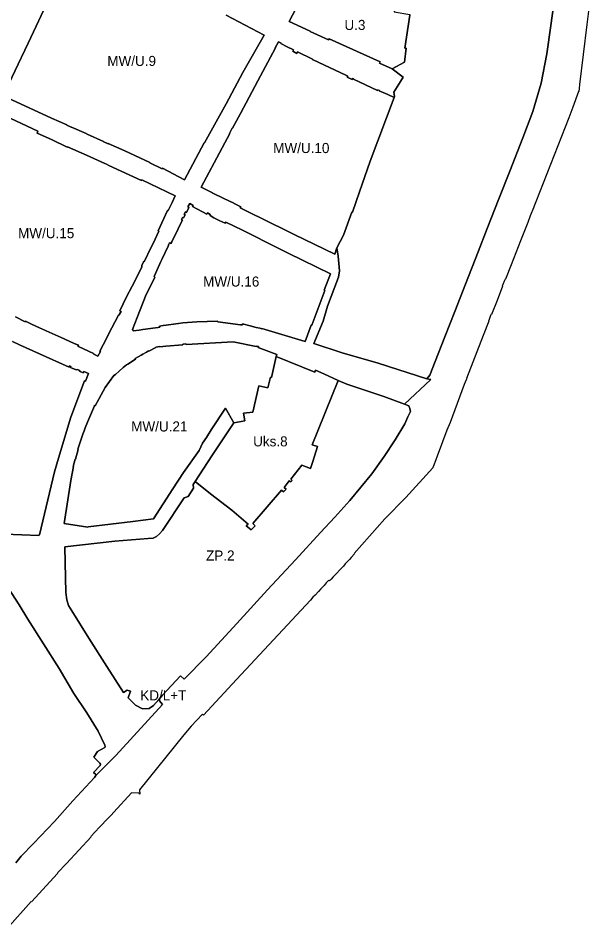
# Model space of a CAD drawing. Extents: x 7423367 to 7424726, y 5546744 to 5548391.
# Drawn here: x 7424194.2 to 7424477, y 5547495 to 5547946.7 of the extents above; entities that cross this region are included whole.
import ezdxf

# ---------------------------------------------------------------- set-up
doc = ezdxf.new("R2010")
doc.units = 0
doc.layers.add('linie_rozgraniczajace', color=7, linetype='Continuous')
doc.layers.add('oznaczenia_przeznaczen', color=7, linetype='Continuous')

msp = doc.modelspace()

# ---------------------------------------------------------------- linework, layer by layer
at = {"layer": 'linie_rozgraniczajace'}
for points in [[(7424328.44, 5547945.05), (7424336.81, 5547960.95), (7424338.1, 5547963.38), (7424338.61, 5547964.34), (7424348.19, 5547959.59), (7424348.95, 5547959.24), (7424350.58, 5547958.76), (7424363.05, 5547955.32), (7424375.68, 5547951.82), (7424380.63, 5547950.44), (7424380.54, 5547949.83), (7424388.26, 5547948.56), (7424388.22, 5547948.28), (7424385.9, 5547931.86), (7424386.56, 5547931.79), (7424385.59, 5547924.92), (7424379.57, 5547921.57), (7424373.24, 5547924.45), (7424373.56, 5547925.07), (7424348.32, 5547936.48), (7424348.05, 5547935.98), (7424338.85, 5547940.14), (7424338.9, 5547940.31)], [(7424284.85, 5547862.9), (7424295.29, 5547882.36), (7424299, 5547889.45), (7424298.86, 5547889.53), (7424300.27, 5547892.21), (7424300.41, 5547892.11), (7424304.33, 5547899.39), (7424312.89, 5547915.61), (7424321.74, 5547931.95), (7424321.57, 5547932.04), (7424323.14, 5547934.93), (7424324.51, 5547934.29), (7424324.4, 5547934.09), (7424327.56, 5547932.51), (7424330.67, 5547930.96), (7424330.33, 5547930.3), (7424332.21, 5547929.21), (7424332.66, 5547930), (7424340.05, 5547926.37), (7424340.26, 5547926.12), (7424340.42, 5547926.05), (7424356.49, 5547918.48), (7424357.58, 5547917.99), (7424357.31, 5547917.42), (7424359.66, 5547916.35), (7424359.91, 5547916.87), (7424360.4, 5547916.65), (7424360.35, 5547916.54), (7424372.26, 5547910.91), (7424372.41, 5547911.23), (7424373.24, 5547910.87), (7424373.16, 5547910.7), (7424377.39, 5547908.85), (7424380.46, 5547907.41), (7424368.61, 5547875.81), (7424363.27, 5547860.53), (7424359.94, 5547850.5), (7424359.58, 5547850.52), (7424355.45, 5547839.05), (7424352.18, 5547832.82), (7424351.08, 5547829.65), (7424330.92, 5547839.45), (7424313.97, 5547847.82), (7424310.72, 5547849.4), (7424304.18, 5547852.67), (7424304.44, 5547853.19), (7424301.24, 5547854.82), (7424301.02, 5547854.9), (7424296.04, 5547857.35), (7424296.01, 5547857.28), (7424290.36, 5547860.05), (7424290.4, 5547860.12)], [(7424250.75, 5547792.24), (7424253.18, 5547798.19), (7424257.58, 5547809.64), (7424258.88, 5547812.13), (7424261.88, 5547818.28), (7424261.51, 5547818.5), (7424264.91, 5547825.95), (7424265.37, 5547827.04), (7424268.63, 5547833.94), (7424268.55, 5547833.97), (7424269.17, 5547835.35), (7424269.88, 5547834.95), (7424270.34, 5547835.84), (7424273.5, 5547842.27), (7424273.42, 5547842.41), (7424275.53, 5547846.58), (7424275.06, 5547846.85), (7424275.62, 5547847.89), (7424276.17, 5547847.61), (7424276.96, 5547849.12), (7424276.4, 5547849.44), (7424277.01, 5547850.58), (7424277.56, 5547850.33), (7424278.81, 5547852.84), (7424278.28, 5547853.1), (7424279.2, 5547854.73), (7424280.92, 5547853.82), (7424280.63, 5547853.23), (7424287.63, 5547849.56), (7424287.93, 5547850.13), (7424289.39, 5547849.34), (7424289.28, 5547848.76), (7424291.05, 5547847.68), (7424293.75, 5547846.39), (7424296.72, 5547844.98), (7424297.03, 5547845.59), (7424305.29, 5547841.54), (7424309.98, 5547839.21), (7424318.74, 5547834.83), (7424328.06, 5547830.13), (7424348.93, 5547819.93), (7424345.89, 5547811.83), (7424346.19, 5547811.71), (7424339.76, 5547794.43), (7424339.45, 5547794.51), (7424336.47, 5547786.35), (7424314.94, 5547792.85), (7424314.89, 5547792.68), (7424313.96, 5547792.89), (7424312.18, 5547793.32), (7424309.21, 5547794.09), (7424305.37, 5547795.12), (7424305.32, 5547794.6), (7424304.43, 5547794.67), (7424293.04, 5547796.04), (7424292.94, 5547796.48), (7424282.68, 5547796.13), (7424275.75, 5547795.66), (7424275.71, 5547795.55), (7424273.67, 5547795.23), (7424272.26, 5547795.06), (7424267.58, 5547794.44), (7424265.99, 5547794.25), (7424264.27, 5547794), (7424264.31, 5547793.41), (7424263.6, 5547793.27), (7424262.17, 5547793.08), (7424255.89, 5547792.24), (7424254.12, 5547791.97), (7424251.26, 5547791.67)], [(7424250.75, 5547792.24), (7424251.26, 5547791.67), (7424254.12, 5547791.97), (7424255.89, 5547792.24), (7424262.17, 5547793.08), (7424263.6, 5547793.27), (7424264.31, 5547793.41), (7424264.27, 5547794), (7424265.99, 5547794.25), (7424267.58, 5547794.44), (7424272.26, 5547795.06), (7424273.67, 5547795.23), (7424275.71, 5547795.55), (7424275.75, 5547795.66), (7424282.68, 5547796.13), (7424292.94, 5547796.48), (7424293.04, 5547796.04), (7424304.43, 5547794.67), (7424305.32, 5547794.6), (7424305.37, 5547795.12), (7424309.21, 5547794.09), (7424312.18, 5547793.32), (7424313.96, 5547792.89), (7424314.89, 5547792.68), (7424314.94, 5547792.85), (7424336.47, 5547786.35), (7424339.45, 5547794.51), (7424339.76, 5547794.43), (7424346.19, 5547811.71), (7424345.89, 5547811.83), (7424348.93, 5547819.93), (7424328.06, 5547830.13), (7424318.74, 5547834.83), (7424309.98, 5547839.21), (7424305.29, 5547841.54), (7424297.03, 5547845.59), (7424296.72, 5547844.98), (7424293.75, 5547846.39), (7424291.05, 5547847.68), (7424289.28, 5547848.76), (7424289.39, 5547849.34), (7424287.93, 5547850.13), (7424287.63, 5547849.56), (7424280.63, 5547853.23), (7424280.92, 5547853.82), (7424279.2, 5547854.73), (7424278.28, 5547853.1), (7424278.81, 5547852.84), (7424277.56, 5547850.33), (7424277.01, 5547850.58), (7424276.4, 5547849.44), (7424276.96, 5547849.12), (7424276.17, 5547847.61), (7424275.62, 5547847.89), (7424275.06, 5547846.85), (7424275.53, 5547846.58), (7424273.42, 5547842.41), (7424273.5, 5547842.27), (7424270.34, 5547835.84), (7424269.88, 5547834.95), (7424269.17, 5547835.35), (7424268.55, 5547833.97), (7424268.63, 5547833.94), (7424265.37, 5547827.04), (7424264.91, 5547825.95), (7424261.51, 5547818.5), (7424261.88, 5547818.28), (7424258.88, 5547812.13), (7424257.58, 5547809.64), (7424253.18, 5547798.19)], [(7424216.89, 5547695.98), (7424220.27, 5547717.38), (7424221.53, 5547724.33), (7424221.34, 5547724.38), (7424222.43, 5547728), (7424222.59, 5547727.95), (7424223.94, 5547732.8), (7424223.68, 5547732.9), (7424226.2, 5547740.38), (7424226.82, 5547742.09), (7424227.37, 5547743.53), (7424228.52, 5547746.32), (7424231.89, 5547754.43), (7424231.99, 5547754.67), (7424232.38, 5547754.4), (7424237.23, 5547763.53), (7424241.59, 5547769.43), (7424242.36, 5547769.95), (7424244.21, 5547771.62), (7424246.26, 5547773.39), (7424247.86, 5547774.72), (7424248.43, 5547775.09), (7424252.35, 5547777.62), (7424252.21, 5547777.9), (7424255.05, 5547779.54), (7424255.98, 5547780.08), (7424257.8, 5547781.12), (7424258.82, 5547781.67), (7424258.87, 5547781.55), (7424262.38, 5547783.28), (7424262.3, 5547783.59), (7424264.28, 5547783.82), (7424264.3, 5547783.64), (7424267.32, 5547784), (7424275.74, 5547784.74), (7424275.73, 5547785.06), (7424277.32, 5547785.18), (7424277.34, 5547784.83), (7424300.65, 5547786.18), (7424312.19, 5547783.8), (7424312.29, 5547784.09), (7424313.22, 5547783.79), (7424313.12, 5547783.37), (7424322.35, 5547779.93), (7424322.03, 5547778.92), (7424319.65, 5547768.47), (7424319.2, 5547768.59), (7424317.95, 5547763.27), (7424313.42, 5547764.35), (7424310.44, 5547751.25), (7424305.79, 5547750.77), (7424306.43, 5547746.92), (7424301.08, 5547746.01), (7424296.95, 5547753.22), (7424289.84, 5547742.47), (7424287.5, 5547738.71), (7424285.48, 5547735.87), (7424283.9, 5547732.34), (7424276.07, 5547721.36), (7424270.83, 5547713.3), (7424261.22, 5547698.43), (7424251, 5547697.09), (7424228.77, 5547694.34), (7424228.74, 5547694.22)], [(7424281.91, 5547716.81), (7424290.17, 5547729.65), (7424301.08, 5547746.01), (7424306.43, 5547746.92), (7424305.79, 5547750.77), (7424310.44, 5547751.25), (7424313.42, 5547764.35), (7424317.95, 5547763.27), (7424319.2, 5547768.59), (7424319.65, 5547768.47), (7424322.03, 5547778.92), (7424341.12, 5547771.13), (7424341.5, 5547772.1), (7424345.6, 5547770.34), (7424352.75, 5547766.97), (7424339.96, 5547735.02), (7424342.57, 5547734.31), (7424340.16, 5547726.73), (7424338.99, 5547723.31), (7424334.71, 5547724.92), (7424329.32, 5547718.03), (7424329.99, 5547717.43), (7424329.3, 5547716.71), (7424328.56, 5547717.25), (7424325.99, 5547713.97), (7424326.96, 5547713.12), (7424325.73, 5547711.81), (7424324.73, 5547712.64), (7424310.42, 5547695.99), (7424311.63, 5547694.94), (7424309.63, 5547692.84), (7424307.17, 5547694.92), (7424308.12, 5547695.8), (7424300.12, 5547702.65), (7424289.49, 5547710.73)], [(7424217.84, 5547661.82), (7424217.47, 5547676.63), (7424217.33, 5547684.47), (7424242, 5547687.36), (7424258.62, 5547688.58), (7424261.1, 5547688.85), (7424262.66, 5547689.54), (7424264.25, 5547690.86), (7424265.65, 5547692.55), (7424276.37, 5547708.76), (7424278.42, 5547709.42), (7424281.08, 5547713.55), (7424280.94, 5547715.47), (7424281.91, 5547716.81), (7424289.49, 5547710.73), (7424300.12, 5547702.65), (7424308.12, 5547695.8), (7424307.17, 5547694.92), (7424309.63, 5547692.84), (7424311.63, 5547694.94), (7424310.42, 5547695.99), (7424324.73, 5547712.64), (7424325.73, 5547711.81), (7424326.96, 5547713.12), (7424325.99, 5547713.97), (7424328.56, 5547717.25), (7424329.3, 5547716.71), (7424329.99, 5547717.43), (7424329.32, 5547718.03), (7424334.71, 5547724.92), (7424338.99, 5547723.31), (7424340.16, 5547726.73), (7424342.57, 5547734.31), (7424339.96, 5547735.02), (7424352.75, 5547766.97), (7424357.12, 5547765.2), (7424369.44, 5547761.02), (7424375.45, 5547759), (7424385.71, 5547755.19), (7424387.84, 5547754.37), (7424388.35, 5547753.1), (7424388.61, 5547751.68), (7424387.3, 5547748.98), (7424385.86, 5547745.41), (7424380.99, 5547737.63), (7424375.6, 5547729.23), (7424369.4, 5547720.65), (7424358.48, 5547707.5), (7424351.07, 5547699.26), (7424344, 5547691.56), (7424331.59, 5547677.99), (7424317.72, 5547663.07), (7424302.48, 5547646.39), (7424287.31, 5547629.96), (7424276.38, 5547618.89), (7424274.62, 5547620.52), (7424265.68, 5547610.81), (7424263.81, 5547608.7), (7424261.25, 5547605.71), (7424259.04, 5547604.35), (7424255.78, 5547604.11), (7424252.27, 5547605.91), (7424248.61, 5547609.56), (7424249.81, 5547612.82), (7424248.13, 5547613.32), (7424246.42, 5547612.29), (7424238.14, 5547625.04), (7424229.17, 5547639.17), (7424220.77, 5547652.73), (7424219.05, 5547655.41), (7424218.18, 5547658.2)]]:
    msp.add_lwpolyline(points, close=True, dxfattribs=at)
for points in [[(7424336.81, 5547960.95), (7424328.44, 5547945.05), (7424338.9, 5547940.31), (7424338.85, 5547940.14), (7424348.05, 5547935.98), (7424348.32, 5547936.48), (7424373.56, 5547925.07), (7424373.24, 5547924.45), (7424379.57, 5547921.57), (7424384.95, 5547917.54), (7424383.6, 5547915.33), (7424380.39, 5547910.04), (7424380.66, 5547907.89), (7424380.46, 5547907.41), (7424377.39, 5547908.85), (7424373.16, 5547910.7), (7424373.24, 5547910.87), (7424372.41, 5547911.23), (7424372.26, 5547910.91), (7424360.35, 5547916.54), (7424360.4, 5547916.65), (7424359.91, 5547916.87), (7424359.66, 5547916.35), (7424357.31, 5547917.42), (7424357.58, 5547917.99), (7424356.49, 5547918.48), (7424340.42, 5547926.05), (7424340.26, 5547926.12), (7424340.05, 5547926.37), (7424332.66, 5547930), (7424332.21, 5547929.21), (7424330.33, 5547930.3), (7424330.67, 5547930.96), (7424327.56, 5547932.51), (7424324.4, 5547934.09), (7424324.51, 5547934.29), (7424323.14, 5547934.93), (7424321.57, 5547932.04), (7424321.74, 5547931.95), (7424312.89, 5547915.61), (7424304.33, 5547899.39), (7424300.41, 5547892.11), (7424300.27, 5547892.21), (7424298.86, 5547889.53), (7424299, 5547889.45), (7424295.29, 5547882.36), (7424284.85, 5547862.9), (7424290.4, 5547860.12), (7424290.36, 5547860.05), (7424296.01, 5547857.28), (7424296.04, 5547857.35), (7424301.02, 5547854.9), (7424301.24, 5547854.82), (7424304.44, 5547853.19), (7424304.18, 5547852.67), (7424310.72, 5547849.4), (7424313.97, 5547847.82), (7424330.92, 5547839.45), (7424351.08, 5547829.65), (7424352.18, 5547832.82), (7424352.77, 5547828.72), (7424353.4, 5547821.42), (7424352.86, 5547818.25), (7424347.48, 5547803.83), (7424345.29, 5547796.46), (7424340.63, 5547785.34), (7424354.75, 5547780.68), (7424372.52, 5547775.54), (7424396.71, 5547767.84), (7424398.78, 5547767.45), (7424385.71, 5547755.19), (7424375.45, 5547759), (7424369.44, 5547761.02), (7424357.12, 5547765.2), (7424352.75, 5547766.97), (7424345.6, 5547770.34), (7424341.5, 5547772.1), (7424341.12, 5547771.13), (7424322.03, 5547778.92), (7424322.35, 5547779.93), (7424313.12, 5547783.37), (7424313.22, 5547783.79), (7424312.29, 5547784.09), (7424312.19, 5547783.8), (7424300.65, 5547786.18), (7424277.34, 5547784.83), (7424277.32, 5547785.18), (7424275.73, 5547785.06), (7424275.74, 5547784.74), (7424267.32, 5547784), (7424264.3, 5547783.64), (7424264.28, 5547783.82), (7424262.3, 5547783.59), (7424262.38, 5547783.28), (7424258.87, 5547781.55), (7424258.82, 5547781.67), (7424257.8, 5547781.12), (7424255.98, 5547780.08), (7424255.05, 5547779.54), (7424252.21, 5547777.9), (7424252.35, 5547777.62), (7424248.43, 5547775.09), (7424247.86, 5547774.72), (7424246.26, 5547773.39), (7424244.21, 5547771.62), (7424242.36, 5547769.95), (7424241.59, 5547769.43), (7424237.23, 5547763.53), (7424232.38, 5547754.4), (7424231.99, 5547754.67), (7424231.89, 5547754.43), (7424228.52, 5547746.32), (7424227.37, 5547743.53), (7424226.82, 5547742.09), (7424226.2, 5547740.38), (7424223.68, 5547732.9), (7424223.94, 5547732.8), (7424222.59, 5547727.95), (7424222.43, 5547728), (7424221.34, 5547724.38), (7424221.53, 5547724.33), (7424220.27, 5547717.38), (7424216.89, 5547695.98), (7424228.74, 5547694.22), (7424228.77, 5547694.34), (7424251, 5547697.09), (7424261.22, 5547698.43), (7424270.83, 5547713.3), (7424276.07, 5547721.36), (7424283.9, 5547732.34), (7424285.48, 5547735.87), (7424287.5, 5547738.71), (7424289.84, 5547742.47), (7424296.95, 5547753.22), (7424301.08, 5547746.01), (7424290.17, 5547729.65), (7424281.91, 5547716.81), (7424280.94, 5547715.47), (7424281.08, 5547713.55), (7424278.42, 5547709.42), (7424276.37, 5547708.76), (7424265.65, 5547692.55), (7424264.25, 5547690.86), (7424262.66, 5547689.54), (7424261.1, 5547688.85), (7424258.62, 5547688.58), (7424242, 5547687.36), (7424217.33, 5547684.47), (7424217.47, 5547676.63), (7424217.84, 5547661.82), (7424218.18, 5547658.2), (7424219.05, 5547655.41), (7424220.77, 5547652.73), (7424229.17, 5547639.17), (7424238.14, 5547625.04), (7424246.42, 5547612.29), (7424248.13, 5547613.32), (7424249.81, 5547612.82), (7424248.61, 5547609.56), (7424252.27, 5547605.91), (7424255.78, 5547604.11), (7424259.04, 5547604.35), (7424261.25, 5547605.71), (7424263.81, 5547608.7), (7424264.24, 5547608.13), (7424265.61, 5547606.33), (7424242.47, 5547580.92), (7424242.04, 5547580.45), (7424232.6, 5547570.96), (7424232.44, 5547571.65), (7424231.48, 5547572.53), (7424234.74, 5547576.01), (7424235, 5547576.74), (7424234.69, 5547577.23), (7424231.69, 5547580.14), (7424233.52, 5547582.94), (7424237.11, 5547585.01), (7424237.34, 5547585.5), (7424237.17, 5547586.08), (7424233.73, 5547593.03), (7424228.18, 5547602.06), (7424221.72, 5547611.72), (7424214.38, 5547624.18), (7424198.95, 5547648.59), (7424194.57, 5547655.72), (7424187.08, 5547667.38)], [(7424192.95, 5547527.74), (7424195.66, 5547530.98), (7424201.75, 5547537.35), (7424212.06, 5547548.28), (7424221.27, 5547558.47), (7424231.89, 5547570), (7424232.6, 5547570.96), (7424242.04, 5547580.45), (7424242.47, 5547580.92), (7424265.61, 5547606.33), (7424264.24, 5547608.13), (7424263.81, 5547608.7), (7424265.68, 5547610.81), (7424274.62, 5547620.52), (7424276.38, 5547618.89), (7424287.31, 5547629.96), (7424302.48, 5547646.39), (7424317.72, 5547663.07), (7424331.59, 5547677.99), (7424344, 5547691.56), (7424351.07, 5547699.26), (7424358.48, 5547707.5), (7424369.4, 5547720.65), (7424375.6, 5547729.23), (7424380.99, 5547737.63), (7424385.86, 5547745.41), (7424387.3, 5547748.98), (7424388.61, 5547751.68), (7424388.35, 5547753.1), (7424387.84, 5547754.37), (7424385.71, 5547755.19), (7424398.78, 5547767.45), (7424396.71, 5547767.84), (7424398.26, 5547769.65), (7424400.87, 5547776.49), (7424405.65, 5547788.64), (7424410.62, 5547801.24), (7424415.88, 5547814.78), (7424422.14, 5547830.76), (7424426.69, 5547842.33), (7424432.48, 5547857.1), (7424437.9, 5547870.91), (7424444.35, 5547887.35), (7424449.22, 5547900.48), (7424453.39, 5547914.49), (7424456.23, 5547929.1), (7424458.14, 5547943.07), (7424460.44, 5547960.03)], [(7424460.44, 5547960.03), (7424458.14, 5547943.07), (7424456.23, 5547929.1), (7424453.39, 5547914.49), (7424449.22, 5547900.48), (7424444.35, 5547887.35), (7424437.9, 5547870.91), (7424432.48, 5547857.1), (7424426.69, 5547842.33), (7424422.14, 5547830.76), (7424415.88, 5547814.78), (7424410.62, 5547801.24), (7424405.65, 5547788.64), (7424400.87, 5547776.49), (7424398.26, 5547769.65), (7424396.71, 5547767.84), (7424372.52, 5547775.54), (7424354.75, 5547780.68), (7424340.63, 5547785.34), (7424345.29, 5547796.46), (7424347.48, 5547803.83), (7424352.86, 5547818.25), (7424353.4, 5547821.42), (7424352.77, 5547828.72), (7424352.18, 5547832.82), (7424355.45, 5547839.05), (7424359.58, 5547850.52), (7424359.94, 5547850.5), (7424363.27, 5547860.53), (7424368.61, 5547875.81), (7424380.46, 5547907.41), (7424380.66, 5547907.89), (7424380.39, 5547910.04), (7424383.6, 5547915.33), (7424384.95, 5547917.54), (7424379.57, 5547921.57), (7424385.59, 5547924.92), (7424386.56, 5547931.79), (7424385.9, 5547931.86), (7424388.22, 5547948.28)], [(7424297.29, 5547948.18), (7424316.09, 5547938.25), (7424305.52, 5547919.83), (7424297.17, 5547904.28), (7424286.47, 5547884.88), (7424286.36, 5547884.94), (7424276.66, 5547866.55), (7424265.65, 5547872.27), (7424265.52, 5547872.01), (7424259.33, 5547874.98), (7424259.42, 5547875.19), (7424247.05, 5547880.85), (7424238.75, 5547884.58), (7424238.7, 5547884.47), (7424236.35, 5547885.52), (7424236.41, 5547885.63), (7424228.28, 5547889.26), (7424228.08, 5547889.36), (7424227.87, 5547889.46), (7424220.51, 5547892.73), (7424220.47, 5547892.66), (7424218.19, 5547893.69), (7424218.24, 5547893.77), (7424210.59, 5547897.18), (7424186.66, 5547908.22), (7424195.58, 5547927.09), (7424195.77, 5547927.38), (7424199.05, 5547934.37), (7424209.56, 5547956.66)], [(7424209.56, 5547956.66), (7424199.05, 5547934.37), (7424195.77, 5547927.38), (7424195.58, 5547927.09), (7424186.66, 5547908.22), (7424210.59, 5547897.18), (7424218.24, 5547893.77), (7424218.19, 5547893.69), (7424220.47, 5547892.66), (7424220.51, 5547892.73), (7424227.87, 5547889.46), (7424228.08, 5547889.36), (7424228.28, 5547889.26), (7424236.41, 5547885.63), (7424236.35, 5547885.52), (7424238.7, 5547884.47), (7424238.75, 5547884.58), (7424247.05, 5547880.85), (7424259.42, 5547875.19), (7424259.33, 5547874.98), (7424265.52, 5547872.01), (7424265.65, 5547872.27), (7424276.66, 5547866.55), (7424286.36, 5547884.94), (7424286.47, 5547884.88), (7424297.17, 5547904.28), (7424305.52, 5547919.83), (7424316.09, 5547938.25), (7424297.29, 5547948.18)], [(7424477.01, 5547951.52), (7424476.01, 5547943.62), (7424474.27, 5547928.77), (7424472.46, 5547913.75), (7424472.22, 5547911.83), (7424472.03, 5547910.35), (7424471.85, 5547910.38), (7424469.05, 5547902.62), (7424467.1, 5547897.3), (7424450.71, 5547855.6), (7424449.8, 5547853.16), (7424449.71, 5547852.92), (7424448.02, 5547848.65), (7424446.72, 5547845.37), (7424444.81, 5547840.44), (7424443.16, 5547836.19), (7424440.85, 5547830.33), (7424439.67, 5547827.29), (7424438.47, 5547824.3), (7424435.68, 5547817.23), (7424435.48, 5547817.3), (7424435.22, 5547816.59), (7424434.38, 5547814.62), (7424434.07, 5547813.86), (7424434.25, 5547813.79), (7424431.57, 5547806.74), (7424428.79, 5547799.81), (7424428.61, 5547799.88), (7424428.33, 5547799.16), (7424427.56, 5547797.17), (7424427.26, 5547796.43), (7424427.44, 5547796.36), (7424424.72, 5547789.25), (7424416.38, 5547768.03), (7424416.58, 5547767.95), (7424416.47, 5547767.67), (7424416.16, 5547767.3), (7424415.24, 5547764.95), (7424408.27, 5547746.17), (7424406.67, 5547742.28), (7424399.68, 5547723.71), (7424386.38, 5547709.01), (7424375.95, 5547698.34), (7424360.71, 5547681.21), (7424360.93, 5547681.02), (7424359.26, 5547679.24), (7424358.31, 5547678.17), (7424356.32, 5547676.03), (7424355.34, 5547674.94), (7424350.34, 5547669.61), (7424349.38, 5547668.51), (7424348.5, 5547667.62), (7424348.2, 5547667.91), (7424346.88, 5547666.57), (7424345.8, 5547665.37), (7424344.2, 5547663.59), (7424343.07, 5547662.37), (7424341.35, 5547660.5), (7424340.29, 5547659.46), (7424339.03, 5547658.09), (7424302.32, 5547618.65), (7424286.03, 5547601.02), (7424285.53, 5547601.48), (7424279.94, 5547595.48), (7424276.22, 5547591.22), (7424254.24, 5547563.88), (7424254.43, 5547561.86), (7424254.18, 5547562.26), (7424250.36, 5547562.52), (7424241.57, 5547552.86), (7424240.17, 5547551.36), (7424238.81, 5547549.83), (7424234.44, 5547545.4), (7424230.15, 5547540.74), (7424230.29, 5547540.62), (7424218.17, 5547527.34), (7424218.05, 5547527.46), (7424213.65, 5547522.72), (7424213.73, 5547522.64), (7424213.6, 5547522.48), (7424200.7, 5547508.36), (7424200.59, 5547508.46), (7424188.52, 5547495)], [(7424182.16, 5547900.77), (7424203.9, 5547890.69), (7424203.62, 5547889.68), (7424210.64, 5547886.48), (7424218.45, 5547882.77), (7424218.52, 5547882.92), (7424228, 5547878.7), (7424237.03, 5547874.57), (7424237.12, 5547874.65), (7424237.85, 5547874.23), (7424239, 5547873.71), (7424251.33, 5547868.06), (7424255.33, 5547866.17), (7424255.51, 5547866.59), (7424271.94, 5547858.67), (7424270.42, 5547855.34), (7424268.99, 5547852.28), (7424268.47, 5547851.24), (7424268.12, 5547851.4), (7424263.47, 5547841.3), (7424263.89, 5547841.07), (7424261.01, 5547834.9), (7424259.95, 5547832.81), (7424256.77, 5547826.15), (7424256.32, 5547825.88), (7424255.51, 5547824.08), (7424255.41, 5547823.31), (7424252.34, 5547816.85), (7424250.7, 5547813.86), (7424247.9, 5547808.41), (7424244.59, 5547801.58), (7424245.11, 5547801.26), (7424244.1, 5547799.37), (7424243.92, 5547799.39), (7424238.98, 5547790.01), (7424237.87, 5547787.77), (7424234.67, 5547781.5), (7424234.88, 5547781.41), (7424233.63, 5547779.1), (7424231.68, 5547780.1), (7424231.4, 5547780.45), (7424224.1, 5547783.81), (7424223.69, 5547783.99), (7424223.96, 5547784.46), (7424223.48, 5547784.67), (7424221.56, 5547785.51), (7424215.52, 5547788.39), (7424208.06, 5547791.66), (7424205.82, 5547792.63), (7424204.98, 5547792.99), (7424200.46, 5547795.09), (7424197.72, 5547796.36), (7424197.55, 5547796.04), (7424192.84, 5547798.55)], [(7424192.84, 5547798.55), (7424197.55, 5547796.04), (7424197.72, 5547796.36), (7424200.46, 5547795.09), (7424204.98, 5547792.99), (7424205.82, 5547792.63), (7424208.06, 5547791.66), (7424215.52, 5547788.39), (7424221.56, 5547785.51), (7424223.48, 5547784.67), (7424223.96, 5547784.46), (7424223.69, 5547783.99), (7424224.1, 5547783.81), (7424231.4, 5547780.45), (7424231.68, 5547780.1), (7424233.63, 5547779.1), (7424234.88, 5547781.41), (7424234.67, 5547781.5), (7424237.87, 5547787.77), (7424238.98, 5547790.01), (7424243.92, 5547799.39), (7424244.1, 5547799.37), (7424245.11, 5547801.26), (7424244.59, 5547801.58), (7424247.9, 5547808.41), (7424250.7, 5547813.86), (7424252.34, 5547816.85), (7424255.41, 5547823.31), (7424255.51, 5547824.08), (7424256.32, 5547825.88), (7424256.77, 5547826.15), (7424259.95, 5547832.81), (7424261.01, 5547834.9), (7424263.89, 5547841.07), (7424263.47, 5547841.3), (7424268.12, 5547851.4), (7424268.47, 5547851.24), (7424268.99, 5547852.28), (7424270.42, 5547855.34), (7424271.94, 5547858.67), (7424255.51, 5547866.59), (7424255.33, 5547866.17), (7424251.33, 5547868.06), (7424239, 5547873.71), (7424237.85, 5547874.23), (7424237.12, 5547874.65), (7424237.03, 5547874.57), (7424228, 5547878.7), (7424218.52, 5547882.92), (7424218.45, 5547882.77), (7424210.64, 5547886.48), (7424203.62, 5547889.68), (7424203.9, 5547890.69), (7424182.16, 5547900.77)], [(7424191.33, 5547786.29), (7424194.83, 5547784.64), (7424204.72, 5547780.14), (7424219.41, 5547773.64), (7424219.66, 5547774.19), (7424220.24, 5547773.94), (7424220.02, 5547773.45), (7424222.93, 5547772.21), (7424223.3, 5547772.51), (7424224.63, 5547771.89), (7424224.54, 5547771.59), (7424226.39, 5547770.73), (7424226.69, 5547771.41), (7424228.95, 5547770.4), (7424227.46, 5547766.69), (7424227.08, 5547766.82), (7424220.3, 5547748.75), (7424214.18, 5547728.46), (7424212.14, 5547721.71), (7424204.67, 5547690.43), (7424204.31, 5547690.16), (7424187.51, 5547690.71)], [(7424187.51, 5547690.71), (7424204.31, 5547690.16), (7424204.67, 5547690.43), (7424212.14, 5547721.71), (7424214.18, 5547728.46), (7424220.3, 5547748.75), (7424227.08, 5547766.82), (7424227.46, 5547766.69), (7424228.95, 5547770.4), (7424226.69, 5547771.41), (7424226.39, 5547770.73), (7424224.54, 5547771.59), (7424224.63, 5547771.89), (7424223.3, 5547772.51), (7424222.93, 5547772.21), (7424220.02, 5547773.45), (7424220.24, 5547773.94), (7424219.66, 5547774.19), (7424219.41, 5547773.64), (7424204.72, 5547780.14), (7424194.83, 5547784.64), (7424191.33, 5547786.29)], [(7424187.08, 5547667.38), (7424194.57, 5547655.72), (7424198.95, 5547648.59), (7424214.38, 5547624.18), (7424221.72, 5547611.72), (7424228.18, 5547602.06), (7424233.73, 5547593.03), (7424237.17, 5547586.08), (7424237.34, 5547585.5), (7424237.11, 5547585.01), (7424233.52, 5547582.94), (7424231.69, 5547580.14), (7424234.69, 5547577.23), (7424235, 5547576.74), (7424234.74, 5547576.01), (7424231.48, 5547572.53), (7424232.44, 5547571.65), (7424232.6, 5547570.96), (7424231.89, 5547570), (7424221.27, 5547558.47), (7424212.06, 5547548.28), (7424201.75, 5547537.35), (7424195.66, 5547530.98), (7424192.95, 5547527.74)]]:
    msp.add_lwpolyline(points, dxfattribs=at)

# ---------------------------------------------------------------- texts
at = {"layer": 'oznaczenia_przeznaczen'}
for s, p in [('U.3', (7424355.89, 5547940.87)), ('MW/U.9', (7424238.32, 5547923.02)), ('MW/U.10', (7424320.58, 5547879.82)), ('MW/U.15', (7424194.09, 5547837.58)), ('MW/U.16', (7424285.82, 5547813.58)), ('MW/U.21', (7424250.18, 5547741.69)), ('Uks.8', (7424310.63, 5547734.3)), ('ZP.2', (7424287.28, 5547677.67)), ('KD/L+T', (7424254.67, 5547608.31))]:
    msp.add_text(s, height=5, dxfattribs=at).set_placement(p)

doc.saveas('drawing.dxf')
